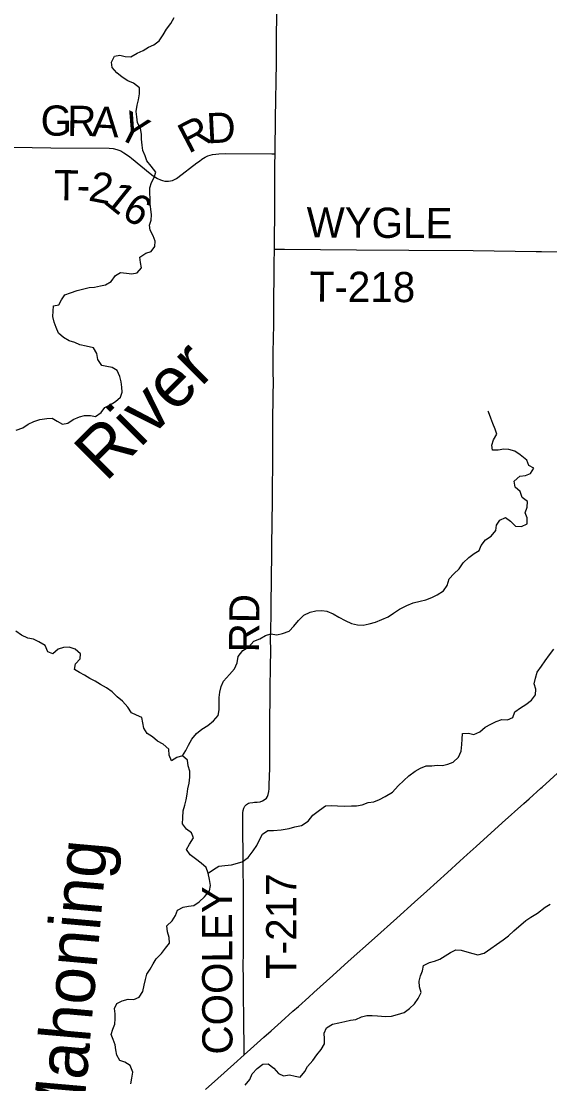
# Model space of a CAD drawing. Extents: x 0 to 34, y 0 to 22.
# Drawn here: x 7.317 to 9.804, y 9.413 to 14.409 of the extents above; entities that cross this region are included whole.
import ezdxf

# ---------------------------------------------------------------- set-up
doc = ezdxf.new("R2010")
doc.units = 0
for name, color, linetype in [('GM_X_Minor_River', 7, 'Continuous'), ('GM_X_Minor_River_Text', 7, 'Continuous'), ('GM_X_State_Route', 7, 'Continuous'), ('GM_X_Township_Road', 7, 'Continuous'), ('GM_X_Township_Road_Text', 7, 'Continuous')]:
    doc.layers.add(name, color=color, linetype=linetype)

msp = doc.modelspace()

# ---------------------------------------------------------------- linework, layer by layer
at = {"layer": 'GM_X_Minor_River'}
for points in [[(7.7357, 12.6051), (7.7602, 12.6206), (7.7845, 12.6408), (7.7919, 12.6647), (7.7906, 12.6884), (7.7866, 12.713), (7.7806, 12.7386), (7.7689, 12.7669), (7.7442, 12.7809), (7.7204, 12.7863), (7.6967, 12.7898), (7.6775, 12.8181), (7.6724, 12.8465), (7.6579, 12.8729), (7.6228, 12.881), (7.5934, 12.8873), (7.5696, 12.8994), (7.542, 12.9066), (7.5163, 12.9215), (7.4924, 12.9431), (7.4817, 12.9686), (7.4719, 12.9941), (7.466, 13.0206), (7.4666, 13.0463), (7.4692, 13.071), (7.4938, 13.0751), (7.5067, 13.0989), (7.5226, 13.1229), (7.549, 13.1327), (7.5801, 13.1425), (7.6113, 13.1505), (7.6368, 13.1565), (7.6623, 13.1587), (7.6897, 13.1647), (7.7143, 13.1697), (7.7406, 13.1862), (7.7602, 13.2139), (7.7846, 13.2285), (7.8121, 13.2241), (7.8368, 13.2215), (7.8623, 13.2265), (7.8829, 13.2505), (7.8788, 13.2751), (7.8757, 13.2998), (7.9029, 13.3191), (7.9284, 13.326), (7.9461, 13.35), (7.9468, 13.3747), (7.9371, 13.4002), (7.9245, 13.4266), (7.9213, 13.4503), (7.9277, 13.4741), (7.9303, 13.4988), (7.9271, 13.5254), (7.924, 13.55), (7.9237, 13.5757), (7.9225, 13.6003), (7.9222, 13.626), (7.9295, 13.6507), (7.9425, 13.6746), (7.9498, 13.6994), (7.9277, 13.7276), (7.9076, 13.7521), (7.9007, 13.7767), (7.89, 13.8022), (7.8859, 13.8268), (7.8828, 13.8543), (7.8834, 13.878), (7.8775, 13.9045), (7.8639, 13.9319), (7.8617, 13.9594), (7.8586, 13.985), (7.863, 14.0145), (7.8693, 14.0402), (7.8738, 14.0678), (7.8734, 14.0963), (7.8457, 14.1187), (7.8182, 14.1288), (7.7915, 14.1456), (7.7666, 14.1672), (7.7446, 14.1916), (7.7424, 14.2162), (7.7553, 14.2449), (7.7808, 14.249), (7.8055, 14.2436), (7.8321, 14.242), (7.8631, 14.2594), (7.8914, 14.2721), (7.9158, 14.2866), (7.9413, 14.2983), (7.9657, 14.3176), (7.9843, 14.3454), (8.0011, 14.3712), (8.0206, 14.398), (8.0374, 14.4267)], [(7.293, 12.486), (7.325, 12.4968), (7.3494, 12.5142), (7.3758, 12.5278), (7.4051, 12.5358), (7.4372, 12.5409), (7.4628, 12.5421), (7.4866, 12.5282), (7.5114, 12.5152), (7.5359, 12.5193), (7.5622, 12.5367), (7.5905, 12.5484), (7.6151, 12.5553), (7.6425, 12.5547), (7.6663, 12.5502), (7.6925, 12.5695), (7.7112, 12.5935), (7.7357, 12.6051)], [(8.0761, 10.9555), (8.0919, 10.9794), (8.1039, 11.0052), (8.1197, 11.0329), (8.1421, 11.0607), (8.1675, 11.0809), (8.1948, 11.0974), (8.221, 11.1195), (8.2435, 11.1445), (8.2479, 11.1721), (8.2485, 11.2015), (8.2491, 11.229), (8.2517, 11.2547), (8.2571, 11.2813), (8.2691, 11.3062), (8.2972, 11.3378), (8.3205, 11.3637), (8.3325, 11.3923), (8.3379, 11.4228), (8.3603, 11.4506), (8.3885, 11.468), (8.4119, 11.4939), (8.4392, 11.5056), (8.4665, 11.5211), (8.491, 11.5281), (8.5204, 11.5246), (8.5469, 11.5297), (8.5771, 11.5405), (8.6005, 11.5645), (8.621, 11.5913), (8.6463, 11.6163), (8.6764, 11.6309), (8.7038, 11.6369), (8.7313, 11.6382), (8.755, 11.6346), (8.7854, 11.6226), (8.8121, 11.6078), (8.8416, 11.592), (8.8711, 11.5771), (8.8996, 11.5708), (8.9252, 11.5702), (8.9535, 11.5762), (8.9837, 11.5842), (9.0139, 11.5969), (9.0431, 11.6086), (9.0694, 11.626), (9.0976, 11.6444), (9.1315, 11.6619), (9.1617, 11.6745), (9.1938, 11.6825), (9.2202, 11.6885), (9.2485, 11.7003), (9.2739, 11.7119), (9.304, 11.7313), (9.3208, 11.7562), (9.3299, 11.7867), (9.3533, 11.8116), (9.3777, 11.8337), (9.3963, 11.8624), (9.4235, 11.8884), (9.4479, 11.9067), (9.4724, 11.9203), (9.4816, 11.9441), (9.5011, 11.97), (9.5275, 11.9883), (9.5499, 12.0152), (9.5534, 12.039), (9.5692, 12.0638), (9.5956, 12.0755), (9.6195, 12.0578), (9.6434, 12.0353), (9.6709, 12.0327), (9.6972, 12.0463), (9.6979, 12.0739), (9.6881, 12.0984), (9.6983, 12.1251), (9.6989, 12.1508), (9.6741, 12.1695), (9.6643, 12.1978), (9.6404, 12.2184), (9.6363, 12.2459), (9.6635, 12.27), (9.689, 12.2731), (9.7135, 12.2829), (9.7294, 12.3078), (9.7056, 12.3198), (9.6958, 12.3454), (9.6652, 12.3706), (9.6395, 12.3884), (9.6119, 12.3956), (9.5873, 12.3972), (9.5608, 12.3922), (9.5352, 12.3928), (9.5321, 12.4165), (9.5385, 12.4403), (9.5553, 12.4671), (9.5474, 12.4917), (9.5367, 12.5182), (9.5269, 12.5427), (9.5162, 12.572), (9.5133, 12.5758)], [(8.0487, 10.9467), (8.0243, 10.9321), (8.0136, 10.9586), (8.0114, 10.9861), (7.9855, 11.0105), (7.9589, 11.0244), (7.935, 11.044), (7.9102, 11.0608), (7.8947, 11.0853), (7.8897, 11.11), (7.8847, 11.1346), (7.859, 11.1457), (7.8352, 11.1577), (7.8179, 11.1841), (7.7939, 11.2123), (7.769, 11.2329), (7.7442, 11.2554), (7.7184, 11.275), (7.6907, 11.2908), (7.665, 11.3057), (7.6393, 11.3187), (7.6155, 11.3345), (7.5916, 11.3466), (7.5678, 11.3615), (7.5723, 11.3872), (7.5947, 11.4112), (7.5963, 11.4349), (7.5705, 11.4574), (7.543, 11.4656), (7.5165, 11.4644), (7.491, 11.4565), (7.4657, 11.4353), (7.4419, 11.4436), (7.4292, 11.4738), (7.3997, 11.4915), (7.3749, 11.5035), (7.3484, 11.508), (7.3179, 11.5228), (7.2912, 11.5415)], [(8.1969, 10.4026), (8.2213, 10.42), (8.2476, 10.4364), (8.2751, 10.4387), (8.3072, 10.4428), (8.3563, 10.4567), (8.3854, 10.477), (8.4078, 10.5076), (8.4255, 10.5334), (8.4375, 10.5602), (8.4524, 10.5869), (8.4777, 10.6034), (8.5033, 10.6046), (8.5402, 10.6069), (8.577, 10.614), (8.6044, 10.621), (8.6365, 10.6271), (8.6676, 10.6474), (8.689, 10.6761), (8.7209, 10.7002), (8.7482, 10.7195), (8.7756, 10.7208), (8.805, 10.7202), (8.8363, 10.7177), (8.8703, 10.72), (8.8949, 10.7203), (8.9214, 10.7253), (8.9487, 10.7361), (8.9762, 10.7393), (9.0026, 10.7491), (9.0298, 10.7646), (9.0637, 10.784), (9.0899, 10.8137), (9.1171, 10.8387), (9.1414, 10.8618), (9.1705, 10.883), (9.195, 10.8966), (9.2223, 10.9083), (9.2498, 10.9086), (9.2744, 10.9117), (9.299, 10.9101), (9.3245, 10.9161), (9.349, 10.925), (9.3743, 10.949), (9.3873, 10.9767), (9.3907, 11.008), (9.3914, 11.0327), (9.393, 11.0593), (9.4214, 11.0616), (9.446, 11.0561), (9.4753, 11.0679), (9.5006, 11.0891), (9.526, 11.1036), (9.5514, 11.1172), (9.5788, 11.1261), (9.6053, 11.1245), (9.6307, 11.1352), (9.639, 11.1619), (9.6662, 11.1812), (9.6916, 11.1957), (9.7179, 11.2169), (9.7365, 11.2418), (9.7381, 11.2684), (9.7312, 11.294), (9.7366, 11.3206), (9.7439, 11.3482), (9.7644, 11.376), (9.7821, 11.4018), (9.8026, 11.4296), (9.8231, 11.4564)], [(7.8331, 9.4131), (7.8375, 9.4398), (7.8429, 9.4683), (7.8293, 9.4985), (7.8045, 9.5153), (7.7807, 9.5226), (7.7672, 9.5471), (7.7621, 9.5727), (7.759, 9.5964), (7.7493, 9.6209), (7.7405, 9.6455), (7.7487, 9.6693), (7.7579, 9.6932), (7.7596, 9.7179), (7.7583, 9.7425), (7.7562, 9.7672), (7.7673, 9.7911), (7.7917, 9.8027), (7.821, 9.8116), (7.8466, 9.8091), (7.872, 9.8208), (7.8888, 9.8475), (7.8951, 9.8761), (7.9014, 9.9037), (7.9087, 9.9284), (7.9236, 9.9523), (7.9384, 9.9772), (7.9524, 10.0011), (7.9767, 10.0261), (7.9954, 10.05), (8.014, 10.0749), (8.0128, 10.1005), (8.0049, 10.127), (8.0027, 10.1564), (8.028, 10.1795), (8.0429, 10.2043), (8.0521, 10.2291), (8.0794, 10.2427), (8.1039, 10.2478), (8.1285, 10.2509), (8.1548, 10.2683), (8.1792, 10.2923), (8.2025, 10.3201), (8.2079, 10.3458), (8.2029, 10.3742), (8.1969, 10.4026), (8.1871, 10.43), (8.1632, 10.4506), (8.1374, 10.4712), (8.1126, 10.4899), (8.0943, 10.5153), (8.1082, 10.5402), (8.1278, 10.5689), (8.119, 10.5934), (8.0942, 10.6102), (8.0759, 10.6347), (8.0775, 10.6632), (8.079, 10.6964), (8.0872, 10.7231), (8.0926, 10.7488), (8.0971, 10.7754), (8.1006, 10.8001), (8.1078, 10.8259), (8.1104, 10.8553), (8.11, 10.8828), (8.1031, 10.9084), (8.1, 10.934), (8.0761, 10.9555), (8.0487, 10.9467)], [(8.37, 9.4071), (8.3934, 9.433), (8.4035, 9.4597), (8.4269, 9.4846), (8.4541, 9.5049), (8.4797, 9.5061), (8.5055, 9.4865), (8.5275, 9.4612), (8.5513, 9.45), (8.5787, 9.4551), (8.6053, 9.4488), (8.63, 9.4434), (8.6515, 9.4711), (8.6644, 9.495), (8.6897, 9.5219), (8.7083, 9.5496), (8.7289, 9.5746), (8.7437, 9.6013), (8.7444, 9.6251), (8.7432, 9.6516), (8.7542, 9.6755), (8.7815, 9.6929), (8.8108, 9.6999), (8.8391, 9.7059), (8.8665, 9.7129), (8.8911, 9.7151), (8.9175, 9.7277), (8.943, 9.7337), (8.9676, 9.734), (8.9932, 9.7324), (9.0311, 9.729), (9.0595, 9.7303), (9.0878, 9.7382), (9.1189, 9.7481), (9.1433, 9.7674), (9.1677, 9.7885), (9.1845, 9.8144), (9.1983, 9.8421), (9.1914, 9.8685), (9.1902, 9.8951), (9.1956, 9.9208), (9.2057, 9.9446), (9.2102, 9.9694), (9.2375, 9.9839), (9.262, 9.989), (9.2865, 9.9988), (9.3119, 10.0142), (9.3373, 10.0307), (9.3618, 10.0433), (9.3874, 10.0408), (9.414, 10.0335), (9.4425, 10.0253), (9.4662, 10.0199), (9.4945, 10.0268), (9.5274, 10.0491), (9.5537, 10.0674), (9.5847, 10.0905), (9.6101, 10.1089), (9.6344, 10.1319), (9.6907, 10.1801), (9.7151, 10.1965), (9.7462, 10.2158), (9.7818, 10.2438), (9.8063, 10.2583)]]:
    msp.add_lwpolyline(points, dxfattribs=at)
at = {"layer": 'GM_X_State_Route'}
msp.add_line((9.7619, 10.803), (9.7675, 10.8081), dxfattribs=at)
for points in [[(9.7675, 10.8081), (9.8403, 10.874)], [(9.6821, 10.7308), (9.7071, 10.7534), (9.7619, 10.803)], [(8.1844, 9.3857), (8.2414, 9.4373), (8.3176, 9.5049), (8.3663, 9.5492), (8.3955, 9.5757), (8.4584, 9.632), (8.4926, 9.6626), (8.5397, 9.7038), (8.5954, 9.7537), (8.6223, 9.7768), (8.6703, 9.8204), (8.6933, 9.8415), (8.7829, 9.9224), (8.8559, 9.9883), (8.9792, 10.0976), (9.0842, 10.1923), (9.1679, 10.2664), (9.2255, 10.3187), (9.3227, 10.4058), (9.3812, 10.4592), (9.4157, 10.4906), (9.4584, 10.529), (9.5806, 10.6394), (9.6821, 10.7308)]]:
    msp.add_lwpolyline(points, dxfattribs=at)
at = {"layer": 'GM_X_Township_Road'}
for points in [[(8.5116, 13.7854), (8.5118, 13.7957), (8.5142, 13.9527), (8.5174, 14.2133), (8.5188, 14.3205), (8.5201, 14.4542)], [(7.2657, 13.8168), (7.2805, 13.8167), (7.4566, 13.8147), (7.7313, 13.8118), (7.7496, 13.8102), (7.7675, 13.8064), (7.776, 13.8033), (7.7858, 13.7991), (7.8003, 13.7906), (7.8131, 13.7819), (7.828, 13.771), (7.8358, 13.7647)], [(7.8358, 13.7647), (7.9233, 13.6938), (7.9383, 13.6824), (7.9501, 13.6747), (7.9584, 13.6701), (7.9728, 13.6636), (7.9818, 13.6605), (7.9926, 13.658), (8.0038, 13.6568), (8.0102, 13.657), (8.0197, 13.6582), (8.029, 13.6608), (8.0378, 13.6644), (8.0476, 13.6696), (8.0542, 13.674), (8.1438, 13.7434), (8.1551, 13.7515), (8.1676, 13.7607), (8.1819, 13.7695), (8.1956, 13.7761), (8.2057, 13.7794), (8.2175, 13.7823), (8.2327, 13.7847), (8.2465, 13.786), (8.2775, 13.787), (8.4962, 13.7855), (8.5116, 13.7854)], [(8.5081, 13.3378), (8.51, 13.5521), (8.5097, 13.5984), (8.5108, 13.7336), (8.5116, 13.7854)], [(8.4409, 10.739), (8.4522, 10.7435), (8.4603, 10.7476), (8.4716, 10.7565), (8.4756, 10.7636), (8.4788, 10.7727), (8.4817, 10.7867), (8.4833, 10.7992), (8.4841, 10.8272), (8.4851, 10.8505), (8.4864, 10.9049), (8.4867, 10.9406), (8.4864, 11.0075), (8.4869, 11.0463), (8.4869, 11.0821), (8.4869, 11.1068), (8.4871, 11.1191), (8.4874, 11.1316), (8.4873, 11.1409), (8.4877, 11.2123), (8.4888, 11.2744), (8.4904, 11.3725), (8.4915, 11.4514), (8.4907, 11.5044), (8.4912, 11.5415), (8.4926, 11.6254), (8.4938, 11.6941), (8.4945, 11.756), (8.4953, 11.811), (8.496, 11.8848), (8.4964, 11.9738), (8.4972, 12.019), (8.4976, 12.0686), (8.4991, 12.1384), (8.4994, 12.1826), (8.4998, 12.2477), (8.5006, 12.2915), (8.5006, 12.3147), (8.5006, 12.3537), (8.5002, 12.3862), (8.5004, 12.4375), (8.5013, 12.4931), (8.5017, 12.5631), (8.5018, 12.6111), (8.502, 12.6405), (8.5024, 12.6621), (8.5034, 12.701), (8.5026, 12.7712), (8.503, 12.8569), (8.5038, 12.9123), (8.505, 12.9884), (8.5057, 13.0863), (8.5054, 13.129), (8.5065, 13.1842), (8.5068, 13.2307), (8.5072, 13.2687), (8.5081, 13.3378)], [(8.5081, 13.3378), (8.5554, 13.3375), (8.8951, 13.3349), (9.1403, 13.3328), (9.4429, 13.3306), (9.7394, 13.3269)], [(9.7394, 13.3269), (9.7647, 13.3266), (9.9863, 13.3215), (10.2921, 13.3151), (10.3764, 13.3155), (10.7029, 13.325), (10.8754, 13.3292), (10.9638, 13.334), (10.9711, 13.3344)], [(8.3663, 9.5492), (8.3662, 9.5675), (8.3659, 9.6063), (8.366, 9.6281), (8.365, 9.6603), (8.365, 9.6726), (8.3644, 9.7112), (8.3639, 9.7534), (8.3632, 9.7967), (8.3634, 9.8246), (8.3635, 9.8512), (8.3625, 9.9109), (8.362, 9.9634), (8.3625, 10.0354), (8.363, 10.0948), (8.3625, 10.1336), (8.3624, 10.1632), (8.3631, 10.2145), (8.3626, 10.2795), (8.3632, 10.3106), (8.3628, 10.3557), (8.3619, 10.4007), (8.3607, 10.4445), (8.3607, 10.4887), (8.3611, 10.5318), (8.3604, 10.5618), (8.3603, 10.6072), (8.3601, 10.639), (8.3596, 10.659), (8.3599, 10.6869), (8.3612, 10.6974), (8.3645, 10.7089), (8.3689, 10.7185), (8.3769, 10.7266), (8.387, 10.7323)], [(8.387, 10.7323), (8.3922, 10.7339), (8.4073, 10.7362), (8.4148, 10.7369), (8.4271, 10.7378), (8.4409, 10.739)]]:
    msp.add_lwpolyline(points, dxfattribs=at)

# ---------------------------------------------------------------- texts
at = {"layer": 'GM_X_Minor_River_Text'}
for s, height, rotation, p in [('River', 0.23687, 44.9725, (7.7149, 12.2395)), ('Mahoning', 0.23682, 84.9771, (7.6016, 9.1642))]:
    msp.add_text(s, height=height, rotation=rotation, dxfattribs=at).set_placement(p)
at = {"layer": 'GM_X_Township_Road_Text'}
for s, height, rotation, p in [('G', 0.142, 359.2678, (7.4075, 13.8721)), ('R', 0.142, 359.2506, (7.5324, 13.8705)), ('A', 0.142, 357.0517, (7.6477, 13.869)), ('Y', 0.142, 333.448, (7.7576, 13.8665)), ('R', 0.142, 27.56, (8.1043, 13.7847)), ('D', 0.142, 2.9155, (8.1923, 13.8345)), ('T', 0.142, 359.5414, (7.4714, 13.5676)), ('2', 0.142, 349.1422, (7.6292, 13.567)), ('1', 0.142, 321.1866, (7.6987, 13.5581)), ('-', 0.142, 359.5439, (7.5777, 13.5668)), ('6', 0.142, 328.3183, (7.7826, 13.4921)), ('WYGLE', 0.14205, 359.6183, (8.6594, 13.393)), ('T-218', 0.14205, 359.7193, (8.6743, 13.0905)), ('RD', 0.14205, 89.5136, (8.4363, 11.4409)), ('T-217', 0.14205, 90, (8.6116, 9.9058)), ('COOLEY', 0.14205, 90.1693, (8.3113, 9.5505))]:
    msp.add_text(s, height=height, rotation=rotation, dxfattribs=at).set_placement(p)

doc.saveas('drawing.dxf')
